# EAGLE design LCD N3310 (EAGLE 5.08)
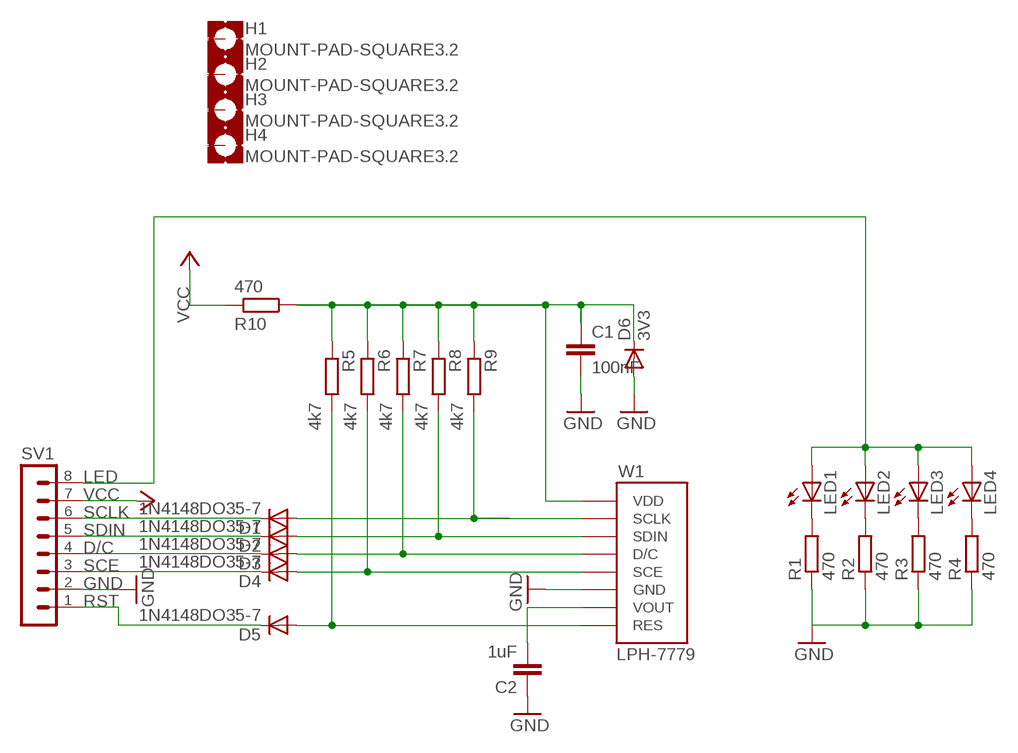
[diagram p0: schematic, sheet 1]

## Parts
C1  100nF  C-EUC1206  [C1206]
C2  1uF  C-EU025_050-025X075  [C025_050-025X075]
D1  1N4148DO35-7  [DO35-7]
D2  1N4148DO35-7  [DO35-7]
D3  1N4148DO35-7  [DO35-7]
D4  1N4148DO35-7  [DO35-7]
D5  1N4148DO35-7  [DO35-7]
D6  3V3  1N4148DO35-7  [DO35-7]
H1  MOUNT-PAD-SQUARE3.2  [3,2-PAD-SQUARE]
H2  MOUNT-PAD-SQUARE3.2  [3,2-PAD-SQUARE]
H3  MOUNT-PAD-SQUARE3.2  [3,2-PAD-SQUARE]
H4  MOUNT-PAD-SQUARE3.2  [3,2-PAD-SQUARE]
LED1  LEDCHIPLED_1206  [CHIPLED_1206]
LED2  LEDCHIPLED_1206  [CHIPLED_1206]
LED3  LEDCHIPLED_1206  [CHIPLED_1206]
LED4  LEDCHIPLED_1206  [CHIPLED_1206]
R1  470  R-EU_M1206  [M1206]
R2  470  R-EU_M1206  [M1206]
R3  470  R-EU_M1206  [M1206]
R4  470  R-EU_M1206  [M1206]
R5  4k7  R-EU_M1206  [M1206]
R6  4k7  R-EU_M1206  [M1206]
R7  4k7  R-EU_M1206  [M1206]
R8  4k7  R-EU_M1206  [M1206]
R9  4k7  R-EU_M1206  [M1206]
R10  470  R-EU_M1206  [M1206]
SV1  MA08-1  [MA08-1]
W1  LPH-7779  [LPH-7779]

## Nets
D/C: D3.C SV1.4
GND: C1.2 C2.1 D6.A R1.1 R2.1 R3.1 R4.1 SV1.2 W1.6GND(GND)
LED: LED1.A LED2.A LED3.A LED4.A SV1.8
N$1: LED1.C R1.2
N$2: LED2.C R2.2
N$3: LED3.C R3.2
N$4: LED4.C R4.2
N$5: D1.A R9.2 W1.2SCLK(SCLK)
N$6: D2.A R8.2 W1.3SDIN(SDIN)
N$7: D3.A R7.2 W1.4D/C(D/C)
N$8: D4.A R6.2 W1.5SCE(SCE)
N$9: D5.A R5.2 W1.8RES(RES)
N$10: C2.2 W1.7VOUT(VOUT)
RST: D5.C SV1.1
SCE: D4.C SV1.3
SCLK: D1.C SV1.6
SDIN: D2.C SV1.5
VCC: R10.2 SV1.7
VDD: C1.1 D6.C R5.1 R6.1 R7.1 R8.1 R9.1 R10.1 W1.1VDD(VDD)
Unconnected: H1.B3,2(MOUNT) H2.B3,2(MOUNT) H3.B3,2(MOUNT) H4.B3,2(MOUNT)

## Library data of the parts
C1 C2 = rcl:C-EU: CAPACITOR, European symbol
D1-D6 = diode:1N4148: DIODE
H1-H4 = holes:MOUNT-PAD-SQUARE: MOUNTING PAD, square
LED1-LED4 = led:LED: LED
R1-R10 = rcl:R-EU_: RESISTOR, European symbol
SV1 = con-lstb:MA08-1: PIN HEADER
W1 = LCD LPH-7779:LPH-7779: LPH-7779 Nokia 3310 displayer.

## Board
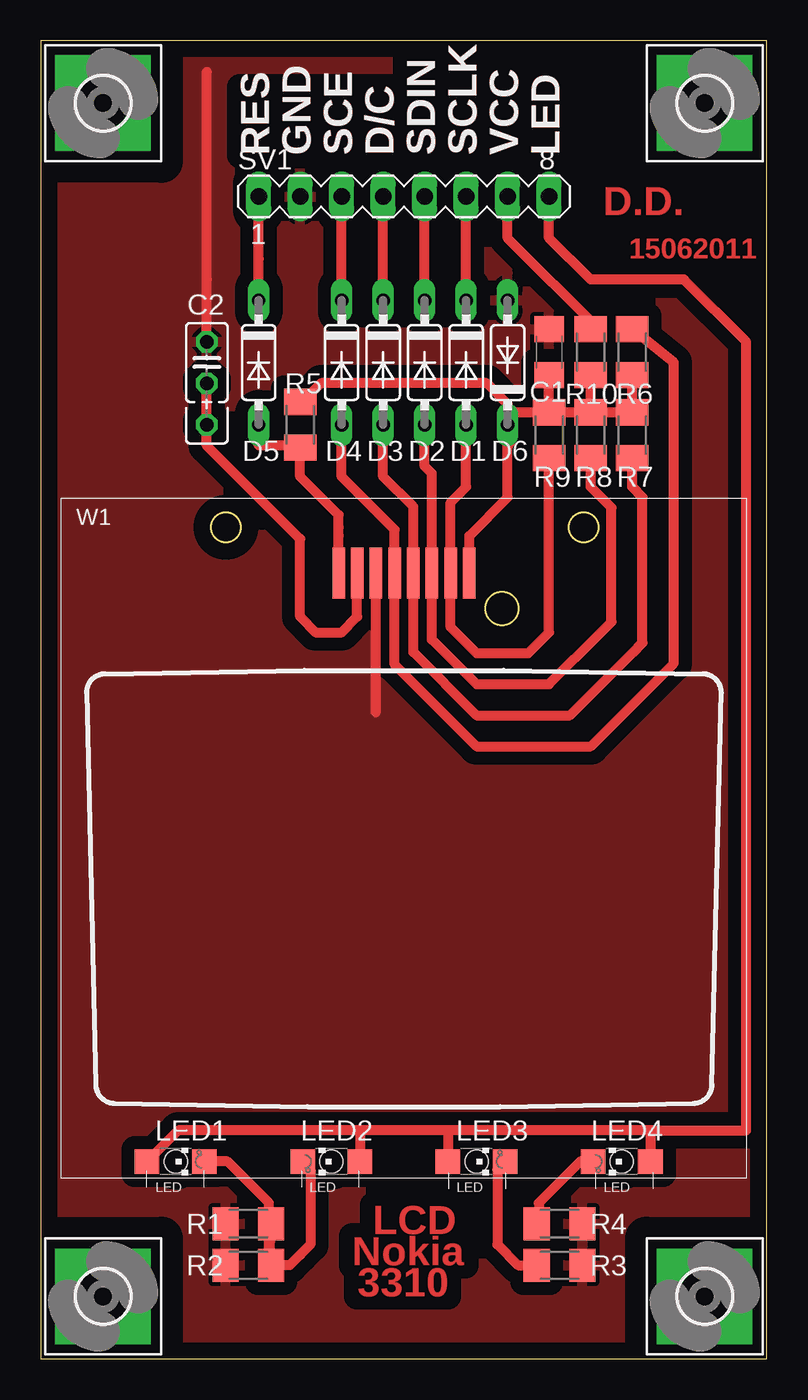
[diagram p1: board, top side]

Size 44.45 x 80.64 mm. Coordinates in mm from the lower left corner, seen from the top.
Outline: 0,0 44.45,0 44.45,80.64 0,80.64 0,0
Copper layers (1*16): Top 0.035mm / dielectric 1.5mm / Bottom 0.035mm
Design rules "default": minimum track width 10mil, minimum drill 24mil, track to track 8mil, track to pad 8mil, pad to pad 8mil, via to via 8mil, smd to smd 8mil, copper to edge 40mil, drill to drill 8mil, minimum pad ring 10mil, minimum via ring 8mil, stop-mask expansion 4mil, vias tented up to drill 0mil, thermal gap 10mil

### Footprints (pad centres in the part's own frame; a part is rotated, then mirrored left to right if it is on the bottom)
C1206 = smd 1.6 x 1.8: 1 -1.4,0; 2 1.4,0
C025_050-025X075 = drill 0.813 octagon: 1 -1.27,0; 2 1.27,0; 3 3.81,0
DO35-7 = drill 0.813 long: A 3.81,0; C -3.81,0
3,2-PAD-SQUARE = drill 3.2 pad 5.842 square: B3,2 0,0
CHIPLED_1206 = smd 1.5 x 1.5: A 0,-1.75; C 0,1.75
M1206 = smd 1.6 x 2: 1 -1.4,0; 2 1.4,0
MA08-1 = drill 1.016 long: 1 -8.89,0; 2 -6.35,0; 3 -3.81,0; 4 -1.27,0; 5 1.27,0; 6 3.81,0; 7 6.35,0; 8 8.89,0
LPH-7779 = smd 0.762 x 3.1: 1VDD 4,17.6; 2SCLK 2.857,17.6; 3SDIN 1.714,17.6; 4D/C 0.572,17.6; 5SCE -0.571,17.6; 6GND -1.714,17.6; 7VOUT -2.857,17.6; 8RES -4,17.6 | hole 1.4: -13.97,-18.415; -4.445,-18.415; 4.445,-18.415; 13.335,-18.415

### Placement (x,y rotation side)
C1  31.12,61.59 90 top
C2  10.16,60.96 270 top
D1  26.04,60.96 270 top
D2  23.5,60.96 270 top
D3  20.96,60.96 270 top
D4  18.42,60.96 270 top
D5  13.34,60.96 270 top
D6  28.58,60.96 90 top
H1  3.81,3.81 0 top
H2  40.64,3.81 0 top
H3  40.64,76.83 0 top
H4  3.81,76.83 0 top
LED1  8.26,12.07 270 top
LED2  17.78,12.07 90 top
LED3  26.67,12.07 270 top
LED4  35.56,12.07 90 top
R1  12.7,8.25 0 top
R2  12.7,5.71 0 top
R3  31.75,5.71 180 top
R4  31.75,8.25 180 top
R5  15.88,57.15 270 top
R6  36.2,61.59 90 top
R7  36.2,56.52 270 top
R8  33.66,56.52 270 top
R9  31.12,56.52 270 top
R10  33.66,61.59 90 top
SV1  22.23,71.12 0 top
W1  22.23,30.48 0 top

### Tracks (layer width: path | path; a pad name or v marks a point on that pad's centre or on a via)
D/C
  Top 0.61: D3.C SV1.4
GND
  Top 0.61: C2.1 10.16,66.04 10.16,78.74 | 20.51,44.26 20.51,39.56 20.51,44.26 | 20.51,44.26 W1.6GND
  pour Top (isolate 0.813): -1.27,81.92 -1.27,-1.9 46.36,-1.9 46.36,81.92
LED
  Top 0.61: SV1.8 31.12,68.58 33.66,66.04 39.37,66.04 43.18,62.23 43.18,13.97 40.01,13.97 37.47,13.97 | 37.47,13.97 24.77,13.97 | 24.77,13.97 19.69,13.97 | 19.69,13.97 8.41,13.97 LED1.A | LED2.A 19.53,13.82 19.69,13.97 | LED3.A 24.92,13.82 24.77,13.97 | LED4.A 37.31,13.82 37.47,13.97
N$1
  Top 0.61: LED1.C 11.43,12.07 13.97,9.53 13.97,6.48 R1.2
N$2
  Top 0.61: R2.2 15.24,5.71 15.88,6.35 16.51,6.98 16.51,11.59 LED2.C
N$3
  Top 0.61: R3.2 29.21,5.71 27.94,6.98 27.94,11.59 LED3.C
N$4
  Top 0.61: LED4.C 33.02,12.07 30.48,9.53 30.48,8.39 R4.2
N$5
  Top 0.61: D1.A 26.04,53.34 25.08,52.39 W1.2SCLK 25.08,44.77 26.67,43.18 29.85,43.18 31.12,44.45 R9.2
N$6
  Top 0.61: D2.A 23.5,54.61 23.94,54.17 W1.3SDIN 23.94,44.01 26.67,41.27 31.12,41.27 34.29,44.45 34.92,45.09 34.92,52.07 33.66,53.34 R8.2
N$7
  Top 0.61: D3.A 20.96,53.98 22.8,52.13 W1.4D/C 22.8,43.24 26.67,39.37 32.39,39.37 36.2,43.18 36.83,43.81 36.83,52.7 36.2,53.34 R7.2
N$8
  Top 0.61: D4.A 18.42,53.98 21.65,50.74 W1.5SCE 21.65,42.48 26.67,37.47 33.66,37.47 38.73,42.55 38.73,60.96 R6.2
N$9
  Top 0.61: W1.8RES 18.23,50.36 18.23,50.86 18.23,51.62 15.88,53.98 R5.2 15.11,55.88 13.97,55.88 13.34,55.88 D5.A
N$10
  Top 0.61: W1.7VOUT 19.37,45.4 18.42,44.45 16.83,44.45 15.88,45.4 15.88,50.16 10.16,55.88 C2.2
RST
  Top 0.61: SV1.1 13.34,69.85 13.34,67.31 D5.C
SCE
  Top 0.61: D4.C SV1.3
SCLK
  Top 0.61: D1.C SV1.6
SDIN
  Top 0.61: D2.C SV1.5
VCC
  Top 0.61: SV1.7 28.58,68.58 34.16,63 R10.2
VDD
  Top 0.61: R8.1 R7.1 R6.1 | R9.1 R8.1 | W1.1VDD 26.23,50.36 28.58,52.7 28.58,55.88 | 28.58,55.88 D6.C 28.58,57.78 | 28.58,57.78 28.58,58.42 27.3,59.69 17.15,59.69 15.88,58.42 R5.1 | 28.58,55.88 28.71,56.01 | R9.1 29.02,57.91 28.58,57.78 | R9.1 C1.1 | R8.1 R10.1

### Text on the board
Top: RES | GND | SCE | D/C | SDIN | SCLK | VCC | LED | D.D. | 15062011 | LCD | Nokia | 3310
tNames: RES | GND | SCE | D/C | SDIN | SCLK | VCC | LED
